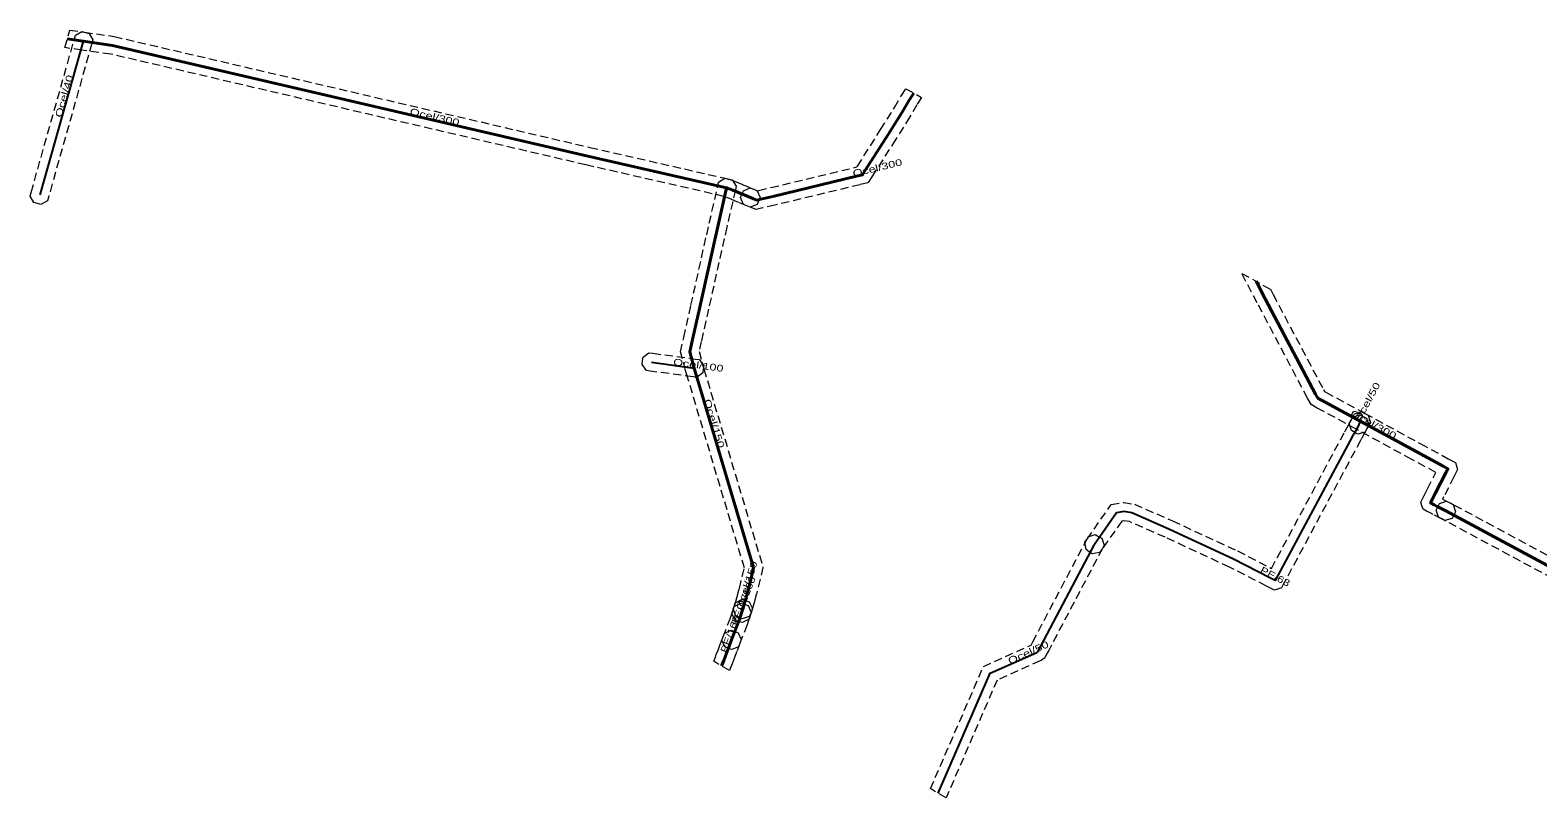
# Model space of a CAD drawing. Extents: x -569813 to -569441, y -1087814 to -1087552.
# Drawn here: x -569812.9 to -569645.3, y -1087637.2 to -1087551.9 of the extents above; entities that cross this region are included whole.
import ezdxf

# ---------------------------------------------------------------- set-up
doc = ezdxf.new("R2010")
doc.units = 0
doc.header["$LTSCALE"] = 0.3
doc.linetypes.add('MEDIUM_DASHED', pattern=[4.5, 3, -1.5])
doc.layers.add('1', color=7, linetype='MEDIUM_DASHED', lineweight=13)
doc.layers.add('24', color=7, linetype='Continuous', lineweight=40)
doc.layers.add('30', color=7, linetype='Continuous')

msp = doc.modelspace()

# ---------------------------------------------------------------- linework, layer by layer
at = {"layer": '1'}
for points in [[(-569805.925, -1087553.009), (-569806.037, -1087553.408), (-569810.848, -1087570.493), (-569810.96, -1087570.892), (-569811.683, -1087571.297), (-569812.082, -1087571.185), (-569812.481, -1087571.073), (-569812.886, -1087570.35), (-569812.774, -1087569.951), (-569807.963, -1087552.866), (-569807.851, -1087552.467), (-569807.128, -1087552.062), (-569806.729, -1087552.174), (-569806.33, -1087552.286)], [(-569809.031, -1087553.862), (-569808.484, -1087551.919), (-569806.86, -1087552.147), (-569803.531, -1087552.624), (-569750.671, -1087564.944), (-569735.182, -1087568.477), (-569734.417, -1087568.778), (-569733.781, -1087569.039), (-569733.551, -1087569.139), (-569733.337, -1087569.226), (-569732.452, -1087569.598), (-569732.071, -1087569.759), (-569731.758, -1087570.526), (-569731.918, -1087570.908), (-569732.079, -1087571.289), (-569732.846, -1087571.602), (-569733.228, -1087571.442), (-569734.103, -1087571.074), (-569734.329, -1087570.981), (-569734.559, -1087570.881), (-569735.163, -1087570.634), (-569735.774, -1087570.393), (-569751.121, -1087566.892), (-569803.901, -1087554.592), (-569807.14, -1087554.127)], [(-569716.035, -1087559.181), (-569715.559, -1087558.426), (-569713.804, -1087559.391), (-569714.325, -1087560.219), (-569715.106, -1087561.55), (-569716.675, -1087564.035), (-569719.254, -1087568.104), (-569719.741, -1087568.879), (-569720.649, -1087569.093), (-569730.102, -1087571.364), (-569731.457, -1087571.673), (-569732.207, -1087571.86), (-569732.868, -1087571.586), (-569733.211, -1087571.448), (-569733.596, -1087571.294), (-569733.922, -1087570.533), (-569733.768, -1087570.149), (-569733.614, -1087569.764), (-569732.853, -1087569.438), (-569732.469, -1087569.592), (-569732.112, -1087569.734), (-569732.051, -1087569.76), (-569731.923, -1087569.727), (-569730.558, -1087569.416), (-569721.111, -1087567.147), (-569720.999, -1087567.121), (-569720.946, -1087567.036), (-569718.365, -1087562.965), (-569716.814, -1087560.51)], [(-569734.76, -1087616.193), (-569734.608, -1087615.89), (-569734.504, -1087615.561), (-569734.333, -1087615.008), (-569734.187, -1087614.434), (-569734.104, -1087614.133), (-569734.058, -1087613.969), (-569733.505, -1087611.677), (-569739.923, -1087590.125), (-569740.033, -1087589.73), (-569740.6, -1087587.676), (-569740.241, -1087586.068), (-569739.438, -1087582.477), (-569737.69, -1087574.649), (-569737.401, -1087573.379), (-569736.453, -1087569.213), (-569736.361, -1087568.809), (-569735.66, -1087568.368), (-569735.256, -1087568.46), (-569734.852, -1087568.552), (-569734.411, -1087569.253), (-569734.503, -1087569.657), (-569735.451, -1087573.823), (-569735.738, -1087575.089), (-569737.486, -1087582.913), (-569738.289, -1087586.504), (-569738.54, -1087587.624), (-569738.105, -1087589.196), (-569738.001, -1087589.573), (-569731.435, -1087611.623), (-569732.122, -1087614.471), (-569732.176, -1087614.667), (-569732.253, -1087614.946), (-569732.407, -1087615.552), (-569732.596, -1087616.159), (-569732.749, -1087616.645), (-569732.786, -1087616.717), (-569732.971, -1087617.088), (-569733.757, -1087617.35), (-569734.127, -1087617.164), (-569734.498, -1087616.979)], [(-569676.494, -1087582.227), (-569678.226, -1087578.953), (-569675.036, -1087580.707), (-569674.726, -1087581.293), (-569669.125, -1087591.895), (-569669.037, -1087592.064), (-569668.876, -1087592.15), (-569664.522, -1087594.511), (-569658.373, -1087597.861), (-569655.276, -1087599.539), (-569654.829, -1087599.778), (-569654.468, -1087599.97), (-569654.223, -1087600.751), (-569654.41, -1087601.115), (-569654.64, -1087601.565), (-569655.779, -1087603.794), (-569655.895, -1087604.023), (-569655.074, -1087604.455), (-569654.707, -1087604.648), (-569654.462, -1087605.439), (-569654.655, -1087605.806), (-569654.848, -1087606.173), (-569655.639, -1087606.418), (-569656.006, -1087606.225), (-569656.952, -1087605.727), (-569657.273, -1087605.562), (-569657.687, -1087605.354), (-569658.06, -1087605.168), (-569658.19, -1087604.772), (-569658.32, -1087604.376), (-569658.13, -1087604.005), (-569657.901, -1087603.556), (-569657.561, -1087602.886), (-569656.636, -1087601.078), (-569659.327, -1087599.619), (-569665.478, -1087596.269), (-569669.824, -1087593.91), (-569670.523, -1087593.536), (-569670.895, -1087592.825)], [(-569744.105, -1087587.768), (-569743.695, -1087587.824), (-569738.934, -1087588.472), (-569738.524, -1087588.528), (-569738.022, -1087589.188), (-569738.078, -1087589.598), (-569738.134, -1087590.008), (-569738.794, -1087590.51), (-569739.204, -1087590.454), (-569743.965, -1087589.806), (-569744.375, -1087589.75), (-569744.877, -1087589.09), (-569744.821, -1087588.68), (-569744.765, -1087588.27)], [(-569663.923, -1087595.503), (-569664.121, -1087595.867), (-569664.311, -1087596.217), (-569664.509, -1087596.581), (-569665.303, -1087596.817), (-569665.667, -1087596.619), (-569666.031, -1087596.421), (-569666.267, -1087595.627), (-569666.069, -1087595.263), (-569665.879, -1087594.913), (-569665.681, -1087594.549), (-569664.887, -1087594.313), (-569664.523, -1087594.511), (-569664.159, -1087594.709)], [(-569678.691, -1087609.791), (-569674.914, -1087611.731), (-569666.78, -1087596.564), (-569666.656, -1087596.338), (-569666.201, -1087595.517), (-569666.077, -1087595.279), (-569665.886, -1087594.911), (-569665.096, -1087594.662), (-569664.729, -1087594.853), (-569664.361, -1087595.044), (-569664.112, -1087595.834), (-569664.303, -1087596.201), (-569664.439, -1087596.463), (-569664.904, -1087597.302), (-569665.02, -1087597.516), (-569673.287, -1087612.929), (-569673.604, -1087613.535), (-569673.795, -1087613.899), (-569674.578, -1087614.148), (-569674.944, -1087613.961), (-569675.475, -1087613.69), (-569679.569, -1087611.589), (-569686.73, -1087608.272), (-569690.715, -1087606.536), (-569691.335, -1087606.434), (-569691.56, -1087606.474), (-569693.782, -1087609.635), (-569694.02, -1087609.974), (-569694.836, -1087610.116), (-569695.175, -1087609.878), (-569695.514, -1087609.64), (-569695.656, -1087608.824), (-569695.418, -1087608.485), (-569692.72, -1087604.646), (-569691.345, -1087604.406), (-569690.145, -1087604.604), (-569685.91, -1087606.448)], [(-569608.794, -1087631.169), (-569609.163, -1087630.981), (-569624.661, -1087623.075), (-569655.534, -1087606.466), (-569655.995, -1087606.231), (-569656.364, -1087606.043), (-569656.619, -1087605.254), (-569656.431, -1087604.885), (-569656.243, -1087604.516), (-569655.454, -1087604.261), (-569655.085, -1087604.449), (-569654.606, -1087604.694), (-569623.733, -1087621.303), (-569608.255, -1087629.199), (-569607.886, -1087629.387), (-569607.63, -1087630.175), (-569607.818, -1087630.544), (-569608.006, -1087630.913)], [(-569711.08, -1087637.23), (-569712.818, -1087636.209), (-569706.934, -1087622.632), (-569701.636, -1087620.262), (-569701.435, -1087619.899), (-569695.485, -1087608.594), (-569695.292, -1087608.227), (-569694.501, -1087607.982), (-569694.134, -1087608.175), (-569693.767, -1087608.368), (-569693.522, -1087609.159), (-569693.715, -1087609.526), (-569699.675, -1087620.849), (-569699.911, -1087621.277), (-569700.12, -1087621.662), (-569700.533, -1087621.972), (-569700.643, -1087622.009), (-569705.408, -1087624.14)], [(-569736.012, -1087619.698), (-569735.86, -1087619.313), (-569735.082, -1087617.342), (-569734.971, -1087617.001), (-569734.848, -1087616.622), (-569734.755, -1087616.353), (-569734.62, -1087615.962), (-569733.874, -1087615.6), (-569733.483, -1087615.735), (-569733.092, -1087615.87), (-569732.73, -1087616.616), (-569732.865, -1087617.007), (-569732.952, -1087617.258), (-569733.069, -1087617.619), (-569733.198, -1087618.018), (-569734, -1087620.047), (-569734.152, -1087620.432), (-569734.912, -1087620.762), (-569735.297, -1087620.61), (-569735.682, -1087620.458)], [(-569734.888, -1087616.773), (-569734.763, -1087616.378), (-569734.633, -1087615.968), (-569734.508, -1087615.573), (-569733.773, -1087615.192), (-569733.378, -1087615.317), (-569732.983, -1087615.442), (-569732.602, -1087616.177), (-569732.727, -1087616.572), (-569732.857, -1087616.982), (-569732.982, -1087617.377), (-569733.717, -1087617.758), (-569734.112, -1087617.633), (-569734.507, -1087617.508)], [(-569735.083, -1087622.866), (-569735.172, -1087623.081), (-569736.914, -1087622.057), (-569736.73, -1087621.593), (-569736.622, -1087621.318), (-569736.425, -1087620.805), (-569736.215, -1087620.247), (-569735.865, -1087619.324), (-569735.718, -1087618.937), (-569734.961, -1087618.598), (-569734.574, -1087618.745), (-569734.187, -1087618.892), (-569733.848, -1087619.649), (-569733.995, -1087620.036), (-569734.345, -1087620.953), (-569734.555, -1087621.515), (-569734.758, -1087622.042), (-569734.87, -1087622.327)]]:
    msp.add_lwpolyline(points, close=True, dxfattribs=at)
at = {"layer": '24', "lineweight": 25}
for p, q in [((-569807, -1087553.137), (-569811.811, -1087570.222)), ((-569743.83, -1087588.815), (-569739.069, -1087589.463)), ((-569665, -1087595.39), (-569665.19, -1087595.74))]:
    msp.add_line(p, q, dxfattribs=at)
at = {"layer": '24'}
msp.add_line((-569733.81, -1087616.68), (-569733.68, -1087616.27), dxfattribs=at)
for points in [[(-569732.84, -1087570.52), (-569733.72, -1087570.15), (-569733.94, -1087570.06), (-569734.17, -1087569.96), (-569734.79, -1087569.706), (-569735.478, -1087569.435), (-569750.896, -1087565.918), (-569803.716, -1087553.608), (-569807, -1087553.137), (-569808.758, -1087552.89)], [(-569732.84, -1087570.52), (-569732.49, -1087570.66), (-569732.129, -1087570.81), (-569731.69, -1087570.7), (-569730.33, -1087570.39), (-569720.88, -1087568.12), (-569720.37, -1087568), (-569720.1, -1087567.57), (-569717.52, -1087563.5), (-569715.96, -1087561.03), (-569715.18, -1087559.7), (-569714.681, -1087558.908)], [(-569735.478, -1087569.435), (-569736.426, -1087573.601), (-569736.714, -1087574.869), (-569738.462, -1087582.695), (-569739.265, -1087586.286), (-569739.57, -1087587.65), (-569739.069, -1087589.463), (-569738.962, -1087589.849), (-569732.47, -1087611.65), (-569733.09, -1087614.22), (-569733.14, -1087614.4), (-569733.22, -1087614.69), (-569733.37, -1087615.28), (-569733.55, -1087615.86), (-569733.679, -1087616.268), (-569733.68, -1087616.27)], [(-569676.631, -1087579.83), (-569675.61, -1087581.76), (-569670.01, -1087592.36), (-569669.78, -1087592.8), (-569669.35, -1087593.03), (-569665, -1087595.39), (-569658.85, -1087598.74), (-569655.75, -1087600.42), (-569655.3, -1087600.66), (-569655.53, -1087601.11), (-569656.67, -1087603.34), (-569657.01, -1087604.01), (-569657.24, -1087604.46), (-569656.82, -1087604.67), (-569656.49, -1087604.84), (-569655.54, -1087605.34)], [(-569608.709, -1087630.09), (-569624.197, -1087622.189), (-569655.07, -1087605.58), (-569655.54, -1087605.34)], [(-569734.93, -1087619.68), (-569734.14, -1087617.68), (-569734.02, -1087617.31), (-569733.9, -1087616.94), (-569733.81, -1087616.68)], [(-569734.93, -1087619.68), (-569735.28, -1087620.6), (-569735.49, -1087621.16), (-569735.69, -1087621.68), (-569735.8, -1087621.96), (-569736.01, -1087622.49), (-569736.043, -1087622.569)]]:
    msp.add_lwpolyline(points, dxfattribs=at)
at = {"layer": '24', "lineweight": 25}
for points in [[(-569665.19, -1087595.74), (-569665.32, -1087595.99), (-569665.78, -1087596.82), (-569665.9, -1087597.04), (-569674.17, -1087612.46), (-569674.49, -1087613.07), (-569675.02, -1087612.8), (-569679.13, -1087610.69), (-569686.32, -1087607.36), (-569690.43, -1087605.57), (-569691.34, -1087605.42), (-569692.14, -1087605.56), (-569694.6, -1087609.06)], [(-569711.949, -1087636.719), (-569706.171, -1087623.386), (-569701.006, -1087621.076), (-569701.003, -1087621.075), (-569700.895, -1087620.994), (-569700.789, -1087620.798), (-569700.555, -1087620.374), (-569694.6, -1087609.06)]]:
    msp.add_lwpolyline(points, dxfattribs=at)

# ---------------------------------------------------------------- texts
at = {"layer": '30'}
for s, rotation, width, p in [('Ocel/40', 74.273, 1.4, (-569809.406, -1087561.679)), ('Ocel/300', 346.881, 1.4, (-569770.745, -1087561.292)), ('Ocel/300', 13.507, 1.4, (-569721.359, -1087568.235)), ('Ocel/100', 352.249, 1.4, (-569741.449, -1087589.139)), ('Ocel/50', 61.504, 1.4, (-569665.095, -1087595.565)), ('Ocel/150', 286.583, 1.4, (-569738.009, -1087593.047)), ('Ocel/300', 331.519, 1.4, (-569666.224, -1087594.726)), ('Ocel/150', 72.408, 1.4, (-569733.73, -1087616.427)), ('PE-O/160', 68.446, 1.3, (-569734.323, -1087618.144)), ('PE/63', 332.825, 1.3, (-569676.255, -1087612.166)), ('PE/160', 69.444, 1.3, (-569735.496, -1087621.174)), ('Ocel/50', 24.096, 1.4, (-569704, -1087622.415))]:
    msp.add_text(s, height=0.75, rotation=rotation, dxfattribs=dict(at, width=width)).set_placement(p)

doc.saveas('drawing.dxf')
